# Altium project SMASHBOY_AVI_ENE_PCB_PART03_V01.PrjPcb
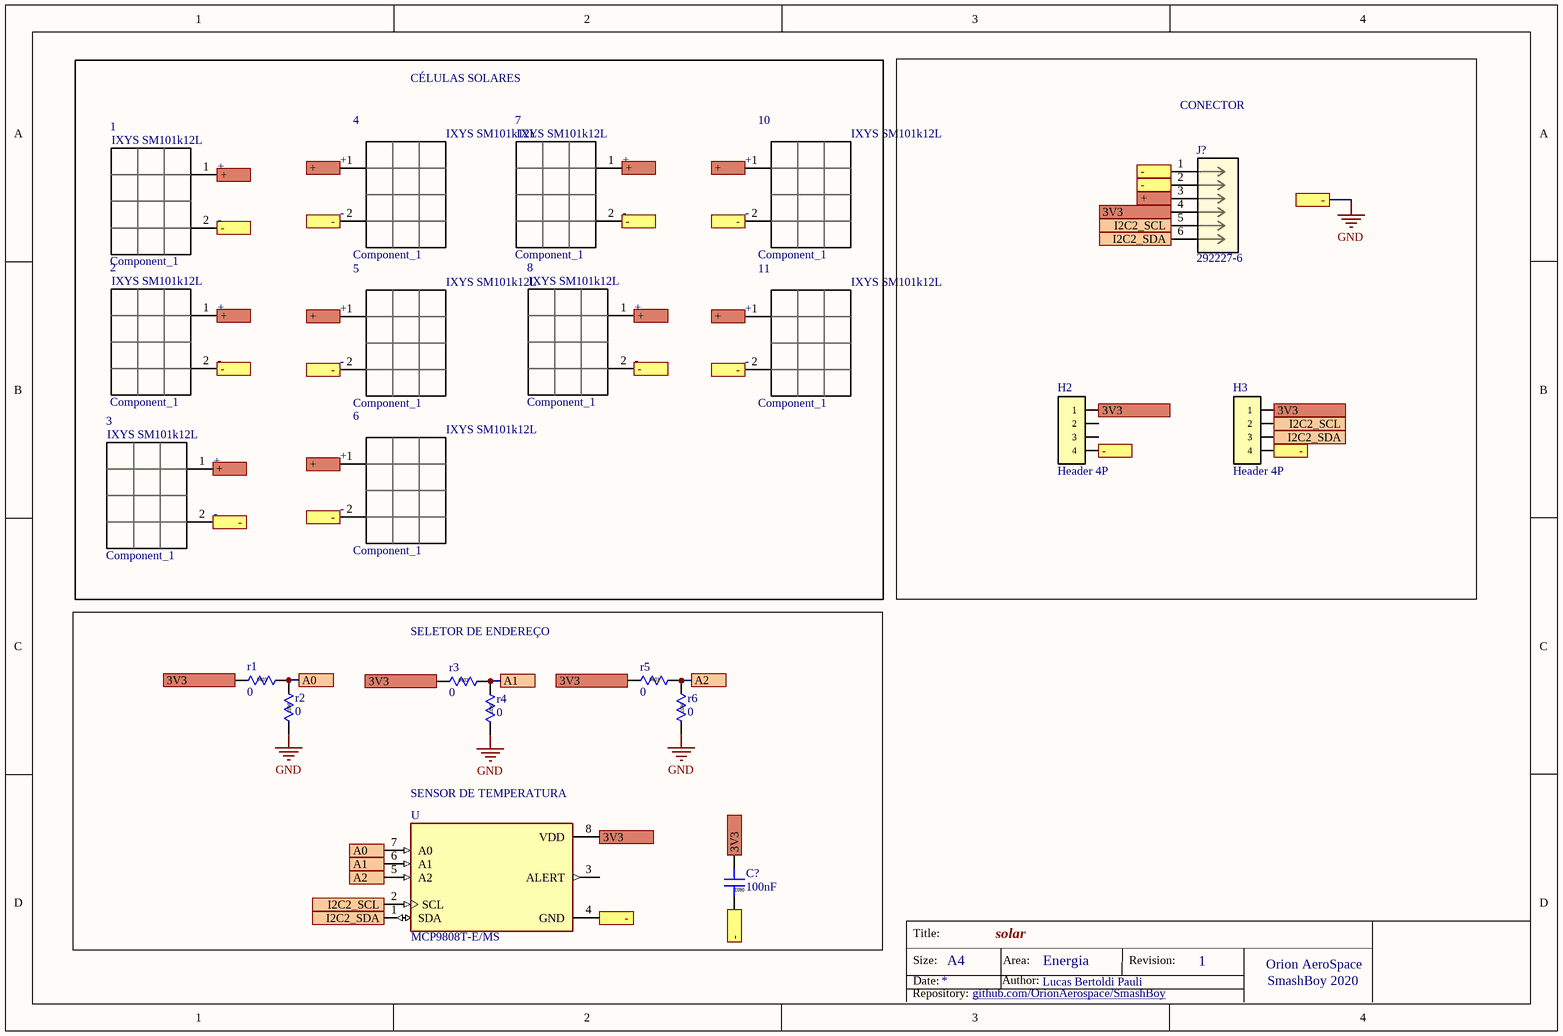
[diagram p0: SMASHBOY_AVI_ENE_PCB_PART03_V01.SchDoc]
1 sheet, 21 parts. Net scope: flat (ports and power ports of the same name join across sheets).
Board file: SMASHBOY_AVI_ENE_PCB_PART03_V01.PcbDoc

## Sheet SMASHBOY_AVI_ENE_PCB_PART03_V01.SchDoc: solar
size A4; Author: Lucas Bertoldi Pauli; Organization: Altium Limited; Address1: L3, 12a Rodborough Rd; Address2: Frenchs Forest; Address3: NSW; Address4: Australia 2086; Revision: 1; AREA: Energia

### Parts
1  Component_1  [PCBComponent_1]
2  Component_1  [PCBComponent_1]
3  Component_1  [PCBComponent_1]
4  Component_1  [PCBComponent_1]
5  Component_1  [PCBComponent_1]
6  Component_1  [PCBComponent_1]
7  Component_1  [PCBComponent_1]
8  Component_1  [PCBComponent_1]
10  Component_1  [PCBComponent_1]
11  Component_1  [PCBComponent_1]
C?  100nF  [CAP0603_060]
H2  Header 4P  [Header-4P]
H3  Header 4P  [Header-4P]
J?  292227-6  [CON6_1X6_DRH_HPI125_TYC]
r1  0  [RES0603]
r2  0  [RES0603]
r3  0  [RES0603]
r4  0  [RES0603]
r5  0  [RES0603]
r6  0  [RES0603]
U  MCP9808T-E/MS  [SOP65P490X110-8N]

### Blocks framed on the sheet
CONECTOR: H2 H3 J?

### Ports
3V3, +, -, A0, A1, A2, I2C2_SCL, I2C2_SDA

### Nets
GND: 1.2(-) 2.2(-) 3.2(-) 4.2(-) 5.2(-) 6.2(-) 7.2(-) 8.2(-) 10.2(-) 11.2(-) C?.1 H2.4 H3.4 J?.1 J?.2 r2.2 r4.2 r6.2 U.4(GND) ; port -
Net1_1: 1.1(+) 2.1(+) 3.1(+) 4.1(+) 5.1(+) 6.1(+) 7.1(+) 8.1(+) 10.1(+) 11.1(+) J?.3 ; port +
NetC?_2: C?.2 H2.1 H3.1 J?.4 r1.1 r3.1 r5.1 U.8(VDD) ; port 3V3
NetH3_2: H3.2 J?.5 U.2(SCL) ; port I2C2_SCL
NetH3_3: H3.3 J?.6 U.1(SDA) ; port I2C2_SDA
Netr1_2: r1.2 r2.1 U.7(A0) ; port A0
Netr3_2: r3.2 r4.1 U.6(A1) ; port A1
Netr5_2: r5.2 r6.1 U.5(A2) ; port A2

Not connected (* = marked no-connect by the designer): H2 2 3; U 3(ALERT)

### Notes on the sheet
- CÉLULAS SOLARES
- SELETOR DE ENDEREÇO
- (near U) SENSOR DE TEMPERATURA

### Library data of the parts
C? = CAP0603: Capacitor SDM 0603
H2 H3 = Header-4P: Header 4 Pinos
J? = 292227-6: No Description Available; Vendor: TE Connectivity; Built_By: EMA_UL_Team; SourceLibrary: Tyco_2012-01-01_HPI_125SRA
r1-r6 = RES0603: Resistor SMD 0603
U = MCP9808T-E/MS: Temperature Sensor Digital, Local -40Â°C ~ 125Â°C 10 b 8-MSOP; MF: Microchip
